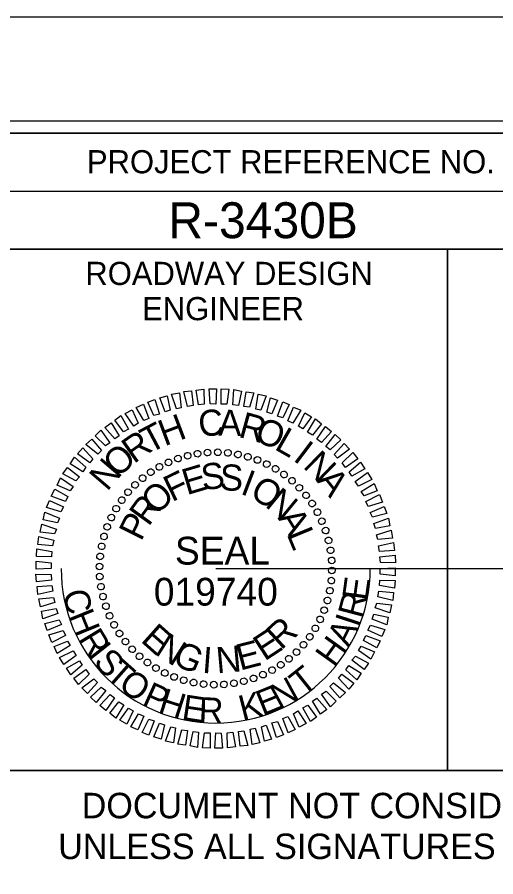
# Model space of a CAD drawing. Extents: x 1260839 to 1262605, y 747346 to 748446.
# Drawn here: x 1262312.9 to 1262416.1, y 748260.2 to 748445.7 of the extents above; entities that cross this region are included whole.
import ezdxf

# ---------------------------------------------------------------- set-up
doc = ezdxf.new("R2010")
doc.units = 0
for name, color, linetype in [('Prop Drainage Structure Bridge', 7, 'Continuous'), ('Prop Drainage Structure Bridge Opening', 7, 'Continuous'), ('Prop Grid Mask', 7, 'Continuous'), ('Prop Horizontal Alignment', 7, 'Continuous'), ('Prop Paved Shoulder', 7, 'Continuous'), ('Prop Terminator CELL', 7, 'Continuous'), ('Prop VPI Label', 7, 'Continuous'), ('Sheet Border Standard 30in CELL', 7, 'Continuous'), ('Sheet Layout Plan Border', 7, 'Continuous')]:
    doc.layers.add(name, color=color, linetype=linetype)

msp = doc.modelspace()

# ---------------------------------------------------------------- linework, layer by layer
at = {"layer": 'Prop Drainage Structure Bridge'}
for p, q in [((1262347.5, 748350.5), (1262347.5, 748350.5)), ((1262349.6, 748351.1), (1262349.6, 748351.1)), ((1262351.8, 748351.5), (1262351.8, 748351.5)), ((1262353.95, 748351.8), (1262353.95, 748351.8)), ((1262356.15, 748351.85), (1262356.15, 748351.85)), ((1262358.35, 748351.7), (1262358.35, 748351.7)), ((1262360.5, 748351.35), (1262360.5, 748351.35)), ((1262362.6, 748350.9), (1262362.6, 748350.9)), ((1262343.55, 748348.7), (1262343.55, 748348.7)), ((1262345.5, 748349.7), (1262345.5, 748349.7)), ((1262364.7, 748350.2), (1262364.7, 748350.2)), ((1262366.7, 748349.3), (1262366.7, 748349.3)), ((1262341.65, 748347.55), (1262341.65, 748347.55)), ((1262368.65, 748348.3), (1262368.65, 748348.3)), ((1262370.45, 748347.05), (1262370.45, 748347.05)), ((1262338.25, 748344.8), (1262338.25, 748344.8)), ((1262339.9, 748346.3), (1262339.9, 748346.3)), ((1262372.2, 748345.7), (1262372.2, 748345.7)), ((1262336.75, 748343.25), (1262336.75, 748343.25)), ((1262373.75, 748344.2), (1262373.75, 748344.2)), ((1262335.4, 748341.5), (1262335.4, 748341.5)), ((1262375.25, 748342.55), (1262375.25, 748342.55)), ((1262334.15, 748339.7), (1262334.15, 748339.7)), ((1262376.5, 748340.8), (1262376.5, 748340.8)), ((1262333.15, 748337.75), (1262333.15, 748337.75)), ((1262377.65, 748338.9), (1262377.65, 748338.9)), ((1262332.25, 748335.75), (1262332.25, 748335.75)), ((1262378.65, 748336.95), (1262378.65, 748336.95)), ((1262331.55, 748333.65), (1262331.55, 748333.65)), ((1262379.45, 748334.95), (1262379.45, 748334.95)), ((1262380.05, 748332.85), (1262380.05, 748332.85)), ((1262331.1, 748331.55), (1262331.1, 748331.55)), ((1262380.45, 748330.65), (1262380.45, 748330.65)), ((1262330.75, 748329.4), (1262330.75, 748329.4)), ((1262380.75, 748328.5), (1262380.75, 748328.5)), ((1262330.6, 748327.2), (1262330.6, 748327.2)), ((1262355.7, 748326.75), (1262355.7, 748326.75)), ((1262380.8, 748326.3), (1262380.8, 748326.3)), ((1262330.65, 748325), (1262330.65, 748325)), ((1262330.95, 748322.85), (1262330.95, 748322.85)), ((1262380.65, 748324.1), (1262380.65, 748324.1)), ((1262380.3, 748321.95), (1262380.3, 748321.95)), ((1262331.35, 748320.65), (1262331.35, 748320.65)), ((1262379.85, 748319.85), (1262379.85, 748319.85)), ((1262331.95, 748318.55), (1262331.95, 748318.55)), ((1262379.15, 748317.75), (1262379.15, 748317.75)), ((1262332.75, 748316.55), (1262332.75, 748316.55)), ((1262378.25, 748315.75), (1262378.25, 748315.75)), ((1262333.75, 748314.6), (1262333.75, 748314.6)), ((1262377.25, 748313.8), (1262377.25, 748313.8)), ((1262334.9, 748312.7), (1262334.9, 748312.7)), ((1262376, 748312), (1262376, 748312)), ((1262336.15, 748310.95), (1262336.15, 748310.95)), ((1262374.65, 748310.25), (1262374.65, 748310.25)), ((1262337.65, 748309.3), (1262337.65, 748309.3)), ((1262339.2, 748307.8), (1262339.2, 748307.8)), ((1262373.15, 748308.7), (1262373.15, 748308.7)), ((1262340.95, 748306.45), (1262340.95, 748306.45)), ((1262369.75, 748305.95), (1262369.75, 748305.95)), ((1262371.5, 748307.2), (1262371.5, 748307.2)), ((1262342.75, 748305.2), (1262342.75, 748305.2)), ((1262344.7, 748304.2), (1262344.7, 748304.2)), ((1262367.85, 748304.8), (1262367.85, 748304.8)), ((1262346.7, 748303.3), (1262346.7, 748303.3)), ((1262348.8, 748302.6), (1262348.8, 748302.6)), ((1262350.9, 748302.15), (1262350.9, 748302.15)), ((1262361.8, 748302.4), (1262361.8, 748302.4)), ((1262363.9, 748303), (1262363.9, 748303)), ((1262365.9, 748303.8), (1262365.9, 748303.8)), ((1262353.05, 748301.8), (1262353.05, 748301.8)), ((1262355.25, 748301.65), (1262355.25, 748301.65)), ((1262357.45, 748301.7), (1262357.45, 748301.7)), ((1262359.6, 748302), (1262359.6, 748302))]:
    msp.add_line(p, q, dxfattribs=at)
for points in [[(1262352, 748362.05), (1262351.45, 748365.25), (1262353.15, 748365.45), (1262353.2, 748362.2)], [(1262354.5, 748362.3), (1262354.25, 748365.55), (1262355.9, 748365.5), (1262355.7, 748362.25)], [(1262356.9, 748362.25), (1262356.9, 748365.5), (1262358.55, 748365.45), (1262358.1, 748362.2)], [(1262359.4, 748362.1), (1262359.6, 748365.35), (1262361.25, 748365.05), (1262360.6, 748361.9)], [(1262344.8, 748360.55), (1262343.65, 748363.55), (1262345.2, 748364), (1262345.85, 748360.9)], [(1262347.2, 748361.2), (1262346.15, 748364.35), (1262347.85, 748364.7), (1262348.25, 748361.45)], [(1262349.6, 748361.75), (1262348.8, 748364.95), (1262350.45, 748365.1), (1262350.8, 748361.9)], [(1262361.8, 748361.7), (1262362.25, 748364.9), (1262363.9, 748364.65), (1262363, 748361.55)], [(1262364.35, 748361.15), (1262364.85, 748364.4), (1262366.55, 748364), (1262365.4, 748360.9)], [(1262366.75, 748360.5), (1262367.5, 748363.6), (1262369.05, 748363.1), (1262367.8, 748360.15)], [(1262340.15, 748358.7), (1262338.55, 748361.5), (1262340.1, 748362.2), (1262341.25, 748359.15)], [(1262342.35, 748359.75), (1262341.05, 748362.65), (1262342.55, 748363.25), (1262343.6, 748360.05)], [(1262369, 748359.6), (1262370.15, 748362.75), (1262371.55, 748362.15), (1262370.15, 748359.25)], [(1262371.25, 748358.65), (1262372.5, 748361.6), (1262374.05, 748360.9), (1262372.35, 748358.1)], [(1262335.8, 748356.25), (1262333.95, 748358.8), (1262335.25, 748359.75), (1262336.9, 748356.85)], [(1262338, 748357.5), (1262336.15, 748360.2), (1262337.7, 748361), (1262338.95, 748358.1)], [(1262373.55, 748357.5), (1262374.9, 748360.35), (1262376.4, 748359.5), (1262374.5, 748356.9)], [(1262333.9, 748354.75), (1262331.75, 748357.15), (1262333.1, 748358.2), (1262334.85, 748355.4)], [(1262375.5, 748356.15), (1262377.25, 748359.05), (1262378.55, 748358), (1262376.6, 748355.55)], [(1262331.9, 748353.2), (1262329.7, 748355.4), (1262330.9, 748356.6), (1262332.85, 748353.9)], [(1262377.55, 748354.65), (1262379.4, 748357.4), (1262380.7, 748356.3), (1262378.5, 748353.95)], [(1262330.25, 748351.45), (1262327.7, 748353.5), (1262328.95, 748354.65), (1262331.05, 748352.25)], [(1262379.45, 748353.1), (1262381.5, 748355.7), (1262382.7, 748354.5), (1262380.4, 748352.35)], [(1262328.5, 748349.55), (1262325.9, 748351.5), (1262327, 748352.8), (1262329.2, 748350.45)], [(1262381.25, 748351.35), (1262383.4, 748353.7), (1262384.6, 748352.5), (1262382, 748350.55)], [(1262327, 748347.65), (1262324.3, 748349.35), (1262325.25, 748350.8), (1262327.65, 748348.6)], [(1262383, 748349.55), (1262385.3, 748351.8), (1262386.35, 748350.45), (1262383.7, 748348.55)], [(1262325.5, 748345.65), (1262322.7, 748347.15), (1262323.7, 748348.55), (1262326.3, 748346.55)], [(1262384.5, 748347.6), (1262386.95, 748349.7), (1262387.9, 748348.25), (1262385.1, 748346.65)], [(1262385.8, 748345.55), (1262388.45, 748347.45), (1262389.4, 748345.95), (1262386.5, 748344.55)], [(1262324.3, 748343.5), (1262321.45, 748344.75), (1262322.2, 748346.3), (1262324.9, 748344.45)], [(1262387.1, 748343.35), (1262389.9, 748345.1), (1262390.55, 748343.55), (1262387.7, 748342.4)], [(1262323.3, 748341.2), (1262320.2, 748342.35), (1262320.95, 748343.9), (1262323.8, 748342.3)], [(1262322.3, 748339), (1262319.2, 748339.9), (1262319.85, 748341.45), (1262322.85, 748340.05)], [(1262388.1, 748341.2), (1262391.05, 748342.7), (1262391.7, 748341.1), (1262388.6, 748340.1)], [(1262389, 748338.85), (1262392.05, 748340.15), (1262392.6, 748338.6), (1262389.5, 748337.8)], [(1262321.55, 748336.6), (1262318.45, 748337.25), (1262318.8, 748338.9), (1262321.95, 748337.65)], [(1262389.8, 748336.45), (1262393, 748337.6), (1262393.3, 748335.95), (1262390.15, 748335.4)], [(1262320.9, 748334.2), (1262317.8, 748334.6), (1262318.15, 748336.3), (1262321.3, 748335.25)], [(1262320.5, 748331.65), (1262317.3, 748331.95), (1262317.5, 748333.65), (1262320.75, 748332.85)], [(1262390.4, 748334.05), (1262393.55, 748335), (1262393.85, 748333.3), (1262390.7, 748333)], [(1262390.85, 748331.65), (1262394.1, 748332.35), (1262394.25, 748330.65), (1262391.05, 748330.45)], [(1262320.25, 748329.25), (1262317, 748329.35), (1262317.1, 748331), (1262320.35, 748330.45)], [(1262320.2, 748326.75), (1262316.95, 748326.6), (1262316.95, 748328.3), (1262320.2, 748327.95)], [(1262391.15, 748329.25), (1262394.4, 748329.65), (1262394.5, 748327.95), (1262391.25, 748328.05)], [(1262391.2, 748326.75), (1262394.45, 748326.9), (1262394.45, 748325.2), (1262391.2, 748325.55)], [(1262320.25, 748324.25), (1262317, 748323.85), (1262316.9, 748325.55), (1262320.15, 748325.45)], [(1262320.55, 748321.85), (1262317.3, 748321.15), (1262317.15, 748322.85), (1262320.35, 748323.05)], [(1262391.15, 748324.25), (1262394.4, 748324.15), (1262394.3, 748322.5), (1262391.05, 748323.05)], [(1262390.9, 748321.85), (1262394.1, 748321.55), (1262393.9, 748319.85), (1262390.65, 748320.65)], [(1262321, 748319.45), (1262317.85, 748318.5), (1262317.55, 748320.2), (1262320.7, 748320.5)], [(1262390.5, 748319.3), (1262393.6, 748318.9), (1262393.25, 748317.2), (1262390.1, 748318.25)], [(1262321.6, 748317.05), (1262318.4, 748315.9), (1262318.1, 748317.55), (1262321.25, 748318.1)], [(1262322.4, 748314.65), (1262319.35, 748313.35), (1262318.8, 748314.9), (1262321.9, 748315.7)], [(1262389.85, 748316.9), (1262392.95, 748316.25), (1262392.6, 748314.6), (1262389.45, 748315.85)], [(1262323.3, 748312.3), (1262320.35, 748310.8), (1262319.7, 748312.4), (1262322.8, 748313.4)], [(1262389.1, 748314.5), (1262392.2, 748313.6), (1262391.55, 748312.05), (1262388.55, 748313.45)], [(1262388.1, 748312.3), (1262391.2, 748311.15), (1262390.45, 748309.6), (1262387.6, 748311.2)], [(1262324.3, 748310.15), (1262321.5, 748308.4), (1262320.85, 748309.95), (1262323.7, 748311.1)], [(1262387.1, 748310), (1262389.95, 748308.75), (1262389.2, 748307.2), (1262386.5, 748309.05)], [(1262325.6, 748307.95), (1262322.95, 748306.05), (1262322, 748307.55), (1262324.9, 748308.95)], [(1262385.9, 748307.85), (1262388.7, 748306.35), (1262387.7, 748304.95), (1262385.1, 748306.95)], [(1262326.9, 748305.9), (1262324.45, 748303.8), (1262323.5, 748305.25), (1262326.3, 748306.85)], [(1262384.4, 748305.85), (1262387.1, 748304.15), (1262386.15, 748302.7), (1262383.75, 748304.9)], [(1262328.4, 748303.95), (1262326.1, 748301.7), (1262325.05, 748303.05), (1262327.7, 748304.95)], [(1262330.15, 748302.15), (1262328, 748299.8), (1262326.8, 748301), (1262329.4, 748302.95)], [(1262382.9, 748303.95), (1262385.5, 748302), (1262384.4, 748300.7), (1262382.2, 748303.05)], [(1262331.95, 748300.4), (1262329.9, 748297.8), (1262328.7, 748299), (1262331, 748301.15)], [(1262379.5, 748300.3), (1262381.7, 748298.1), (1262380.5, 748296.9), (1262378.55, 748299.6)], [(1262381.15, 748302.05), (1262383.7, 748300), (1262382.45, 748298.85), (1262380.35, 748301.25)], [(1262333.85, 748298.85), (1262332, 748296.1), (1262330.7, 748297.2), (1262332.9, 748299.55)], [(1262377.5, 748298.75), (1262379.65, 748296.35), (1262378.3, 748295.3), (1262376.55, 748298.1)], [(1262335.9, 748297.35), (1262334.15, 748294.45), (1262332.85, 748295.5), (1262334.8, 748297.95)], [(1262337.85, 748296), (1262336.5, 748293.15), (1262335, 748294), (1262336.9, 748296.6)], [(1262375.6, 748297.25), (1262377.45, 748294.7), (1262376.15, 748293.75), (1262374.5, 748296.65)], [(1262340.15, 748294.85), (1262338.9, 748291.9), (1262337.35, 748292.6), (1262339.05, 748295.4)], [(1262371.25, 748294.8), (1262372.85, 748292), (1262371.3, 748291.3), (1262370.15, 748294.35)], [(1262373.4, 748296), (1262375.25, 748293.3), (1262373.7, 748292.5), (1262372.45, 748295.4)], [(1262342.4, 748293.9), (1262341.25, 748290.75), (1262339.85, 748291.35), (1262341.25, 748294.25)], [(1262344.65, 748293), (1262343.9, 748289.9), (1262342.35, 748290.4), (1262343.6, 748293.35)], [(1262366.6, 748292.95), (1262367.75, 748289.95), (1262366.2, 748289.5), (1262365.55, 748292.6)], [(1262369.05, 748293.75), (1262370.35, 748290.85), (1262368.85, 748290.25), (1262367.8, 748293.45)], [(1262347.05, 748292.35), (1262346.55, 748289.1), (1262344.85, 748289.5), (1262346, 748292.6)], [(1262349.6, 748291.8), (1262349.15, 748288.6), (1262347.5, 748288.85), (1262348.4, 748291.95)], [(1262352, 748291.4), (1262351.8, 748288.15), (1262350.15, 748288.45), (1262350.8, 748291.6)], [(1262354.5, 748291.25), (1262354.5, 748288), (1262352.85, 748288.05), (1262353.3, 748291.3)], [(1262356.9, 748291.2), (1262357.15, 748287.95), (1262355.5, 748288), (1262355.7, 748291.25)], [(1262359.4, 748291.45), (1262359.95, 748288.25), (1262358.25, 748288.05), (1262358.2, 748291.3)], [(1262361.8, 748291.75), (1262362.6, 748288.55), (1262360.95, 748288.4), (1262360.6, 748291.6)], [(1262364.2, 748292.3), (1262365.25, 748289.15), (1262363.55, 748288.8), (1262363.15, 748292.05)]]:
    msp.add_lwpolyline(points, close=True, dxfattribs=at)
for centre, major_axis in [((1262351.78, 748351.52), (-0.113, 0.711)), ((1262353.95, 748351.77), (-0.05, 0.718)), ((1262356.14, 748351.83), (0.013, 0.72)), ((1262358.32, 748351.7), (0.075, 0.716)), ((1262345.5, 748349.66), (-0.293, 0.658)), ((1262347.54, 748350.47), (-0.234, 0.681)), ((1262349.64, 748351.09), (-0.174, 0.699)), ((1262360.49, 748351.37), (0.137, 0.707)), ((1262362.62, 748350.86), (0.198, 0.692)), ((1262364.69, 748350.17), (0.258, 0.672)), ((1262343.54, 748348.69), (-0.349, 0.63)), ((1262366.7, 748349.29), (0.316, 0.647)), ((1262368.62, 748348.25), (0.371, 0.617)), ((1262339.92, 748346.24), (-0.453, 0.56)), ((1262341.68, 748347.55), (-0.403, 0.597)), ((1262370.44, 748347.04), (0.423, 0.582)), ((1262338.28, 748344.79), (-0.5, 0.518)), ((1262372.16, 748345.68), (0.472, 0.543)), ((1262373.74, 748344.17), (0.518, 0.5)), ((1262336.77, 748343.21), (-0.543, 0.472)), ((1262375.19, 748342.54), (0.56, 0.453)), ((1262335.41, 748341.49), (-0.582, 0.423)), ((1262376.5, 748340.78), (0.597, 0.403)), ((1262334.21, 748339.67), (-0.617, 0.371)), ((1262377.64, 748338.91), (0.63, 0.349)), ((1262333.16, 748337.75), (-0.647, 0.316)), ((1262378.61, 748336.95), (0.658, 0.293)), ((1262332.29, 748335.74), (-0.672, 0.258)), ((1262379.42, 748334.92), (0.681, 0.234)), ((1262331.59, 748333.67), (-0.692, 0.198)), ((1262331.08, 748331.54), (-0.707, 0.137)), ((1262380.04, 748332.82), (0.699, 0.174)), ((1262330.76, 748329.37), (-0.716, 0.075)), ((1262380.47, 748330.68), (0.711, 0.113)), ((1262380.72, 748328.5), (0.718, 0.05)), ((1262330.63, 748327.19), (-0.72, 0.013)), ((1262380.78, 748326.32), (0.72, -0.013)), ((1262330.68, 748325), (-0.718, -0.05)), ((1262380.65, 748324.13), (0.716, -0.075)), ((1262330.93, 748322.83), (-0.711, -0.113)), ((1262380.32, 748321.97), (0.707, -0.137)), ((1262331.37, 748320.69), (-0.699, -0.174)), ((1262331.99, 748318.59), (-0.681, -0.234)), ((1262379.81, 748319.84), (0.692, -0.198)), ((1262332.79, 748316.55), (-0.658, -0.293)), ((1262379.12, 748317.76), (0.672, -0.258)), ((1262333.77, 748314.59), (-0.63, -0.349)), ((1262378.24, 748315.76), (0.647, -0.316)), ((1262334.91, 748312.73), (-0.597, -0.403)), ((1262377.2, 748313.84), (0.617, -0.371)), ((1262336.21, 748310.97), (-0.56, -0.453)), ((1262375.99, 748312.01), (0.582, -0.423)), ((1262337.66, 748309.33), (-0.518, -0.5)), ((1262374.63, 748310.3), (0.543, -0.472)), ((1262339.25, 748307.82), (-0.472, -0.543)), ((1262371.49, 748307.26), (0.453, -0.56)), ((1262373.12, 748308.71), (0.5, -0.518)), ((1262340.96, 748306.46), (-0.423, -0.582)), ((1262342.79, 748305.26), (-0.371, -0.617)), ((1262369.73, 748305.96), (0.403, -0.597)), ((1262344.71, 748304.21), (-0.316, -0.647)), ((1262346.71, 748303.34), (-0.258, -0.672)), ((1262365.9, 748303.84), (0.293, -0.658)), ((1262367.86, 748304.82), (0.349, -0.63)), ((1262348.79, 748302.64), (-0.198, -0.692)), ((1262350.92, 748302.13), (-0.137, -0.707)), ((1262353.08, 748301.81), (-0.075, -0.716)), ((1262355.27, 748301.68), (-0.013, -0.72)), ((1262357.45, 748301.73), (0.05, -0.718)), ((1262359.63, 748301.98), (0.113, -0.711)), ((1262361.77, 748302.42), (0.174, -0.699)), ((1262363.87, 748303.04), (0.234, -0.681))]:
    msp.add_ellipse(centre, major_axis=major_axis, ratio=0.999708, dxfattribs=at)
at = {"layer": 'Prop Drainage Structure Bridge Opening'}
msp.add_line((1262522.75, 748445.74), (1260838.75, 748445.74), dxfattribs=at)
at = {"layer": 'Prop Grid Mask'}
for q in [(1262604.94, 748326.75), (1262355.7, 748326.75)]:
    msp.add_line((1262355.7, 748326.75), q, dxfattribs=at)
at = {"layer": 'Prop Horizontal Alignment'}
msp.add_arc((1262355.7, 748326.75), 33.36, 180, 360, dxfattribs=at)
at = {"layer": 'Prop Paved Shoulder'}
for p, q in [((1262305.7, 748408.19), (1262505.75, 748408.19)), ((1262405.75, 748395.69), (1262405.75, 748283.24))]:
    msp.add_line(p, q, dxfattribs=at)
for points in [[(1262505.75, 748420.74), (1261005.75, 748420.74), (1261005.75, 747370.74), (1262505.75, 747370.74)], [(1262305.7, 748420.74), (1262505.75, 748420.74), (1262505.75, 748395.69), (1262305.7, 748395.69)], [(1262305.7, 748395.69), (1262405.75, 748395.69), (1262405.75, 748283.19), (1262305.7, 748283.19)], [(1262405.75, 748395.69), (1262505.75, 748395.69), (1262505.75, 748283.19), (1262405.75, 748283.19)]]:
    msp.add_lwpolyline(points, close=True, dxfattribs=at)
at = {"layer": 'Prop Terminator CELL'}
msp.add_lwpolyline([(1262518.25, 748423.29), (1260851.75, 748423.29), (1260851.75, 747368.19), (1262518.25, 747368.19)], close=True, dxfattribs=at)
at = {"layer": 'Prop VPI Label'}
msp.add_lwpolyline([(1262522.75, 748445.74), (1260838.75, 748445.74), (1260838.75, 747345.74), (1262522.75, 747345.74)], close=True, dxfattribs=at)
at = {"layer": 'Sheet Layout Plan Border'}
msp.add_line((1262305.7, 748283.19), (1262505.74, 748283.19), dxfattribs=at)

# ---------------------------------------------------------------- texts
at = {"layer": 'Prop Drainage Structure Bridge'}
for s, height, rotation, p in [('H', 5.64, 20.6195, (1262344.65, 748353.1)), ('C', 5.64, 6.2199, (1262352.25, 748355.1)), ('A', 5.64, 359.0203, (1262356.2, 748355.4)), ('R', 5.64, 344.6211, (1262360.4, 748355.2)), ('T', 5.64, 27.8198, (1262341.4, 748351.45)), ('O', 5.64, 337.4212, (1262363.75, 748354.45)), ('R', 5.64, 35.0205, (1262338, 748349.25)), ('L', 5.64, 330.2209, (1262368.15, 748352.6)), ('I', 5.64, 323.0201, (1262372.2, 748350.2)), ('O', 5.64, 42.2217, (1262334.55, 748346.15)), ('N', 5.64, 315.8189, (1262374.35, 748348.65)), ('N', 5.64, 49.4235, (1262332.25, 748343.25)), ('E', 5.64, 16.6111, (1262349.45, 748342.55)), ('S', 5.64, 7.2556, (1262352.9, 748343.6)), ('S', 5.64, 357.9004, (1262356.5, 748343.65)), ('F', 5.64, 25.967, (1262346.25, 748341.05)), ('I', 5.64, 339.1896, (1262360.8, 748342.95)), ('A', 5.64, 308.6172, (1262377.3, 748345.7)), ('O', 5.64, 44.6812, (1262342.95, 748338.1)), ('O', 5.64, 329.8335, (1262362.8, 748342.25)), ('N', 5.64, 320.4766, (1262366.15, 748340.25)), ('R', 5.64, 54.0397, (1262341.2, 748335.65)), ('P', 5.64, 63.3989, (1262339.6, 748332.45)), ('A', 5.64, 301.7603, (1262369, 748337.65)), ('L', 5.64, 292.4008, (1262370.95, 748334.2)), ('SEAL', 5.998, 360, (1262346.9, 748327.6)), ('019740', 5.998, 360, (1262342.34, 748318.74)), ('E', 5.5, 82.1825, (1262388.41, 748319.66)), ('C', 5.5, 283.2464, (1262322.63, 748321.62)), ('R', 5.5, 75.2561, (1262387.31, 748315.76)), ('H', 5.5, 292.1191, (1262323.82, 748316.58)), ('R', 5.64, 42.4814, (1262369.8, 748309)), ('I', 5.5, 71.7356, (1262386.58, 748313.84)), ('R', 5.5, 301.3639, (1262325.87, 748311.59)), ('E', 5.64, 318.2769, (1262339.3, 748311.1)), ('E', 5.64, 33.1241, (1262366.25, 748306.65)), ('A', 5.5, 63.5498, (1262384.42, 748309.58)), ('N', 5.64, 327.634, (1262342.3, 748308.4)), ('H', 5.5, 54.305, (1262381.29, 748305.19)), ('I', 5.5, 308.2904, (1262327.92, 748308.11)), ('G', 5.64, 336.9902, (1262346.1, 748306.15)), ('I', 5.64, 355.7012, (1262352.65, 748304.25)), ('N', 5.64, 5.0564, (1262356, 748304.1)), ('E', 5.64, 14.4118, (1262360.95, 748304.7)), ('S', 5.5, 311.8108, (1262329.11, 748306.44)), ('T', 5.5, 318.5942, (1262331.7, 748303.44)), ('T', 5.5, 38.5631, (1262374.48, 748299.05)), ('O', 5.5, 324.8909, (1262334.4, 748300.94)), ('P', 5.5, 335.5954, (1262339.57, 748297.44)), ('N', 5.5, 28.6314, (1262369.42, 748296.23)), ('H', 5.5, 342.1784, (1262343.03, 748295.78)), ('K', 5.5, 14.3778, (1262361.49, 748293.79)), ('E', 5.5, 22.0484, (1262365.83, 748294.86)), ('E', 5.5, 351.4232, (1262348.17, 748294.15)), ('R', 5.5, 358.0062, (1262351.96, 748293.5))]:
    msp.add_text(s, height=height, rotation=rotation, dxfattribs=at).set_placement(p)
at = {"layer": 'Prop Paved Shoulder'}
for s, height, p in [('PROJECT REFERENCE NO.', 5.0001, (1262327.9, 748412.04)), ('ROADWAY DESIGN', 5.0001, (1262327.56, 748387.94)), ('ENGINEER', 5, (1262339.81, 748380.34))]:
    msp.add_text(s, height=height, dxfattribs=at).set_placement(p)
at = {"layer": 'Sheet Border Standard 30in CELL'}
msp.add_text('R-3430B', height=7.75, dxfattribs=at).set_placement((1262345.47, 748398.04))
at = {"layer": 'Sheet Layout Plan Border'}
for s, p in [('DOCUMENT NOT CONSIDERED FINAL', (1262326.78, 748272.84)), ('UNLESS ALL SIGNATURES COMPLETED', (1262321.7, 748264.04))]:
    msp.add_text(s, height=5.5, dxfattribs=at).set_placement(p)

doc.saveas('drawing.dxf')
